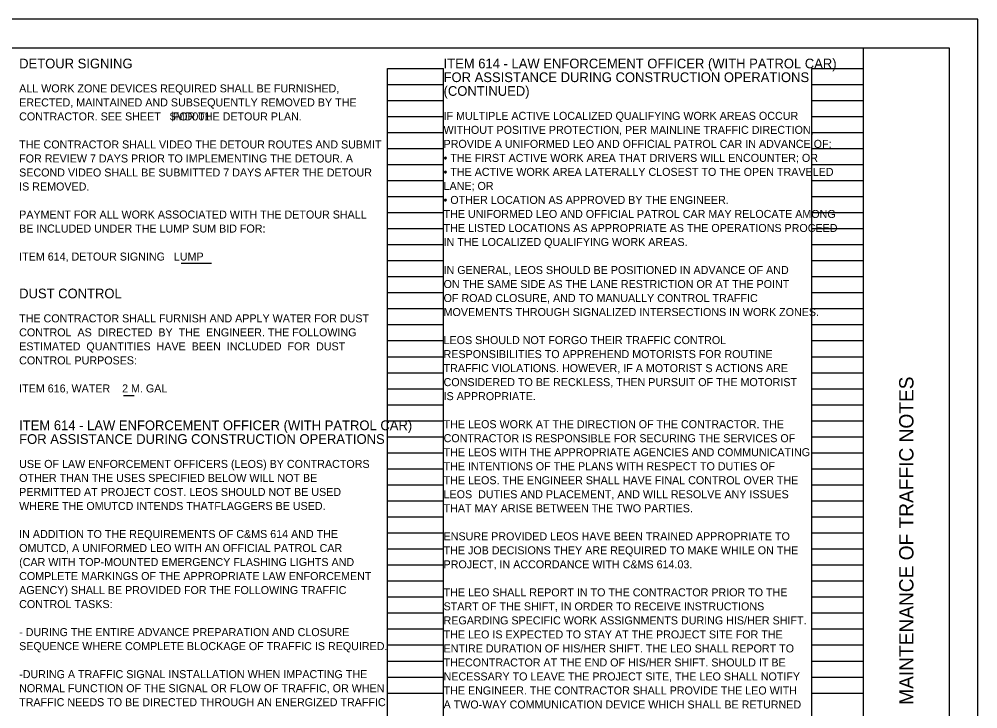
# Model space of a CAD drawing. Extents: x 0 to 69, y 0 to 22.
# Drawn here: x 17.24 to 34, y 9.94 to 22 of the extents above; entities that cross this region are included whole.
import ezdxf

# ---------------------------------------------------------------- set-up
doc = ezdxf.new("R2010")
doc.units = 0
for name, color, linetype in [('GM_X_City_Street', 7, 'Continuous'), ('GM_X_Corporation_Text', 7, 'Continuous'), ('SH_Border', 7, 'Continuous'), ('SH_Cut_Line', 7, 'Continuous'), ('SH_Data', 7, 'Continuous'), ('SH_Text', 7, 'Continuous')]:
    doc.layers.add(name, color=color, linetype=linetype)

msp = doc.modelspace()

# ---------------------------------------------------------------- linework, layer by layer
at = {"layer": 'GM_X_City_Street'}
for p, q in [((23.68, 0.98), (23.68, 21.14)), ((23.68, 21.14), (24.66, 21.14)), ((24.66, 0.98), (24.66, 21.14)), ((31.1, 0.98), (31.1, 21.14)), ((31.1, 21.14), (32, 21.14)), ((32, 0.98), (32, 21.14)), ((23.68, 20.86), (24.66, 20.86)), ((31.1, 20.86), (32, 20.86)), ((23.68, 20.58), (24.66, 20.58)), ((31.1, 20.58), (32, 20.58)), ((23.68, 20.3), (24.66, 20.3)), ((31.1, 20.3), (32, 20.3)), ((23.68, 20.02), (24.66, 20.02)), ((31.1, 20.02), (32, 20.02)), ((23.68, 19.74), (24.66, 19.74)), ((31.1, 19.74), (32, 19.74)), ((23.68, 19.46), (24.66, 19.46)), ((31.1, 19.46), (32, 19.46)), ((23.68, 19.18), (24.66, 19.18)), ((31.1, 19.18), (32, 19.18)), ((23.68, 18.9), (24.66, 18.9)), ((31.1, 18.9), (32, 18.9)), ((23.68, 18.62), (24.66, 18.62)), ((31.1, 18.62), (32, 18.62)), ((23.68, 18.34), (24.66, 18.34)), ((31.1, 18.34), (32, 18.34)), ((23.68, 18.06), (24.66, 18.06)), ((31.1, 18.06), (32, 18.06)), ((23.68, 17.78), (24.66, 17.78)), ((31.1, 17.78), (32, 17.78)), ((23.68, 17.5), (24.66, 17.5)), ((31.1, 17.5), (32, 17.5)), ((23.68, 17.22), (24.66, 17.22)), ((31.1, 17.22), (32, 17.22)), ((23.68, 16.94), (24.66, 16.94)), ((31.1, 16.94), (32, 16.94)), ((23.68, 16.66), (24.66, 16.66)), ((31.1, 16.66), (32, 16.66)), ((23.68, 16.38), (24.66, 16.38)), ((31.1, 16.38), (32, 16.38)), ((23.68, 16.1), (24.66, 16.1)), ((31.1, 16.1), (32, 16.1)), ((23.68, 15.82), (24.66, 15.82)), ((31.1, 15.82), (32, 15.82)), ((23.68, 15.54), (24.66, 15.54)), ((31.1, 15.54), (32, 15.54)), ((23.68, 15.26), (24.66, 15.26)), ((31.1, 15.26), (32, 15.26)), ((23.68, 14.98), (24.66, 14.98)), ((31.1, 14.98), (32, 14.98)), ((23.68, 14.7), (24.66, 14.7)), ((31.1, 14.7), (32, 14.7)), ((23.68, 14.42), (24.66, 14.42)), ((31.1, 14.42), (32, 14.42)), ((23.68, 14.14), (24.66, 14.14)), ((31.1, 14.14), (32, 14.14)), ((23.68, 13.86), (24.66, 13.86)), ((31.1, 13.86), (32, 13.86)), ((23.68, 13.58), (24.66, 13.58)), ((31.1, 13.58), (32, 13.58)), ((23.68, 13.3), (24.66, 13.3)), ((31.1, 13.3), (32, 13.3)), ((23.68, 13.02), (24.66, 13.02)), ((31.1, 13.02), (32, 13.02)), ((23.68, 12.74), (24.66, 12.74)), ((31.1, 12.74), (32, 12.74)), ((23.68, 12.46), (24.66, 12.46)), ((31.1, 12.46), (32, 12.46)), ((23.68, 12.18), (24.66, 12.18)), ((31.1, 12.18), (32, 12.18)), ((23.68, 11.9), (24.66, 11.9)), ((31.1, 11.9), (32, 11.9)), ((23.68, 11.62), (24.66, 11.62)), ((31.1, 11.62), (32, 11.62)), ((23.68, 11.34), (24.66, 11.34)), ((31.1, 11.34), (32, 11.34)), ((23.68, 11.06), (24.66, 11.06)), ((31.1, 11.06), (32, 11.06)), ((23.68, 10.78), (24.66, 10.78)), ((31.1, 10.78), (32, 10.78)), ((23.68, 10.5), (24.66, 10.5)), ((31.1, 10.5), (32, 10.5)), ((23.68, 10.22), (24.66, 10.22)), ((31.1, 10.22), (32, 10.22))]:
    msp.add_line(p, q, dxfattribs=at)
at = {"layer": 'GM_X_Corporation_Text'}
for p, q in [((20.072, 17.735), (20.603, 17.735)), ((19.067, 15.42), (19.248, 15.42))]:
    msp.add_line(p, q, dxfattribs=at)
at = {"layer": 'SH_Border'}
msp.add_line((32, 0.5), (32, 21.5), dxfattribs=at)
msp.add_lwpolyline([(1.5, 21.5), (33.5, 21.5), (33.5, 0.5), (1.5, 0.5)], close=True, dxfattribs=at)
at = {"layer": 'SH_Cut_Line'}
msp.add_lwpolyline([(0, 0), (34, 0), (34, 22), (0, 22)], close=True, dxfattribs=at)

# ---------------------------------------------------------------- texts
at = {"layer": 'SH_Data'}
msp.add_text('MAINTENANCE OF TRAFFIC NOTES', height=0.25, rotation=90, dxfattribs=at).set_placement((32.875, 10.014))
at = {"layer": 'SH_Text'}
for s, height, p in [('DETOUR SIGNING', 0.17, (17.24, 21.14)), ('ITEM 614 - LAW ENFORCEMENT OFFICER (WITH PATROL CAR)', 0.17, (24.66, 21.14)), ('FOR ASSISTANCE DURING CONSTRUCTION OPERATIONS', 0.17, (24.66, 20.9)), ('ALL WORK ZONE DEVICES REQUIRED SHALL BE FURNISHED, ', 0.14, (17.24, 20.72)), ('(CONTINUED)', 0.17, (24.66, 20.66)), ('ERECTED, MAINTAINED AND SUBSEQUENTLY REMOVED BY THE ', 0.14, (17.24, 20.475)), ('CONTRACTOR. SEE SHEET    FOR THE DETOUR PLAN.', 0.14, (17.24, 20.23)), ('$MD001', 0.14, (19.873, 20.23)), ('IF MULTIPLE ACTIVE LOCALIZED QUALIFYING WORK AREAS OCCUR ', 0.14, (24.66, 20.24)), ('WITHOUT POSITIVE PROTECTION, PER MAINLINE TRAFFIC DIRECTION, ', 0.14, (24.66, 19.995)), ('THE CONTRACTOR SHALL VIDEO THE DETOUR ROUTES AND SUBMIT ', 0.14, (17.24, 19.74)), ('PROVIDE A UNIFORMED LEO AND OFFICIAL PATROL CAR IN ADVANCE OF:', 0.14, (24.66, 19.75)), ('FOR REVIEW 7 DAYS PRIOR TO IMPLEMENTING THE DETOUR. A ', 0.14, (17.24, 19.495)), ('• THE FIRST ACTIVE WORK AREA THAT DRIVERS WILL ENCOUNTER; OR', 0.14, (24.66, 19.505)), ('SECOND VIDEO SHALL BE SUBMITTED 7 DAYS AFTER THE DETOUR ', 0.14, (17.24, 19.25)), ('• THE ACTIVE WORK AREA LATERALLY CLOSEST TO THE OPEN TRAVELED ', 0.14, (24.66, 19.26)), ('IS REMOVED.', 0.14, (17.24, 19.005)), ('LANE; OR', 0.14, (24.66, 19.015)), ('• OTHER LOCATION AS APPROVED BY THE ENGINEER.', 0.14, (24.66, 18.77)), ('PAYMENT FOR ALL WORK ASSOCIATED WITH THE DETOUR SHALL ', 0.14, (17.24, 18.515)), ('THE UNIFORMED LEO AND OFFICIAL PATROL CAR MAY RELOCATE AMONG ', 0.14, (24.66, 18.525)), ('BE INCLUDED UNDER THE LUMP SUM BID FOR:', 0.14, (17.24, 18.27)), ('THE LISTED LOCATIONS AS APPROPRIATE AS THE OPERATIONS PROCEED ', 0.14, (24.66, 18.28)), ('IN THE LOCALIZED QUALIFYING WORK AREAS.', 0.14, (24.66, 18.035)), ('ITEM 614, DETOUR SIGNING   LUMP', 0.14, (17.24, 17.78)), ('IN GENERAL, LEOS SHOULD BE POSITIONED IN ADVANCE OF AND ', 0.14, (24.66, 17.545)), ('ON THE SAME SIDE AS THE LANE RESTRICTION OR AT THE POINT ', 0.14, (24.66, 17.3)), ('DUST CONTROL', 0.17, (17.24, 17.12)), ('OF ROAD CLOSURE, AND TO MANUALLY CONTROL TRAFFIC ', 0.14, (24.66, 17.055)), ('MOVEMENTS THROUGH SIGNALIZED INTERSECTIONS IN WORK ZONES.', 0.14, (24.66, 16.81)), ('THE CONTRACTOR SHALL FURNISH AND APPLY WATER FOR DUST', 0.14, (17.24, 16.7)), ('CONTROL  AS  DIRECTED  BY  THE  ENGINEER. THE FOLLOWING', 0.14, (17.24, 16.455)), ('LEOS SHOULD NOT FORGO THEIR TRAFFIC CONTROL ', 0.14, (24.66, 16.32)), ('ESTIMATED  QUANTITIES  HAVE  BEEN  INCLUDED  FOR  DUST', 0.14, (17.24, 16.21)), ('CONTROL PURPOSES: ', 0.14, (17.24, 15.965)), ('RESPONSIBILITIES TO APPREHEND MOTORISTS FOR ROUTINE ', 0.14, (24.66, 16.075)), ('TRAFFIC VIOLATIONS. HOWEVER, IF A MOTORIST S ACTIONS ARE ', 0.14, (24.66, 15.83)), ('ITEM 616, WATER    2 M. GAL ', 0.14, (17.24, 15.475)), ('CONSIDERED TO BE RECKLESS, THEN PURSUIT OF THE MOTORIST ', 0.14, (24.66, 15.585)), ('IS APPROPRIATE.', 0.14, (24.66, 15.34)), ('ITEM 614 - LAW ENFORCEMENT OFFICER (WITH PATROL CAR)', 0.17, (17.24, 14.815)), ('THE LEOS WORK AT THE DIRECTION OF THE CONTRACTOR. THE ', 0.14, (24.66, 14.85)), ('FOR ASSISTANCE DURING CONSTRUCTION OPERATIONS', 0.17, (17.24, 14.575)), ('CONTRACTOR IS RESPONSIBLE FOR SECURING THE SERVICES OF ', 0.14, (24.66, 14.605)), ('THE LEOS WITH THE APPROPRIATE AGENCIES AND COMMUNICATING ', 0.14, (24.66, 14.36)), ('USE OF LAW ENFORCEMENT OFFICERS (LEOS) BY CONTRACTORS ', 0.14, (17.24, 14.155)), ('THE INTENTIONS OF THE PLANS WITH RESPECT TO DUTIES OF ', 0.14, (24.66, 14.115)), ('OTHER THAN THE USES SPECIFIED BELOW WILL NOT BE ', 0.14, (17.24, 13.91)), ('THE LEOS. THE ENGINEER SHALL HAVE FINAL CONTROL OVER THE', 0.14, (24.66, 13.87)), ('PERMITTED AT PROJECT COST. LEOS SHOULD NOT BE USED ', 0.14, (17.24, 13.665)), ('LEOS  DUTIES AND PLACEMENT, AND WILL RESOLVE ANY ISSUES ', 0.14, (24.66, 13.625)), ('WHERE THE OMUTCD INTENDS THATFLAGGERS BE USED.', 0.14, (17.24, 13.42)), ('THAT MAY ARISE BETWEEN THE TWO PARTIES.', 0.14, (24.66, 13.38)), ('IN ADDITION TO THE REQUIREMENTS OF C&MS 614 AND THE ', 0.14, (17.24, 12.93)), ('ENSURE PROVIDED LEOS HAVE BEEN TRAINED APPROPRIATE TO ', 0.14, (24.66, 12.89)), ('OMUTCD, A UNIFORMED LEO WITH AN OFFICIAL PATROL CAR ', 0.14, (17.24, 12.685)), ('THE JOB DECISIONS THEY ARE REQUIRED TO MAKE WHILE ON THE ', 0.14, (24.66, 12.645)), ('(CAR WITH TOP-MOUNTED EMERGENCY FLASHING LIGHTS AND ', 0.14, (17.24, 12.44)), ('PROJECT, IN ACCORDANCE WITH C&MS 614.03.', 0.14, (24.66, 12.4)), ('COMPLETE MARKINGS OF THE APPROPRIATE LAW ENFORCEMENT ', 0.14, (17.24, 12.195)), ('AGENCY) SHALL BE PROVIDED FOR THE FOLLOWING TRAFFIC ', 0.14, (17.24, 11.95)), ('THE LEO SHALL REPORT IN TO THE CONTRACTOR PRIOR TO THE ', 0.14, (24.66, 11.91)), ('CONTROL TASKS:', 0.14, (17.24, 11.705)), ('START OF THE SHIFT, IN ORDER TO RECEIVE INSTRUCTIONS ', 0.14, (24.66, 11.665)), ('REGARDING SPECIFIC WORK ASSIGNMENTS DURING HIS/HER SHIFT. ', 0.14, (24.66, 11.42)), ('- DURING THE ENTIRE ADVANCE PREPARATION AND CLOSURE ', 0.14, (17.24, 11.215)), ('THE LEO IS EXPECTED TO STAY AT THE PROJECT SITE FOR THE ', 0.14, (24.66, 11.175)), ('SEQUENCE WHERE COMPLETE BLOCKAGE OF TRAFFIC IS REQUIRED.', 0.14, (17.24, 10.97)), ('ENTIRE DURATION OF HIS/HER SHIFT. THE LEO SHALL REPORT TO ', 0.14, (24.66, 10.93)), ('THECONTRACTOR AT THE END OF HIS/HER SHIFT. SHOULD IT BE ', 0.14, (24.66, 10.685)), ('-DURING A TRAFFIC SIGNAL INSTALLATION WHEN IMPACTING THE ', 0.14, (17.24, 10.48)), ('NECESSARY TO LEAVE THE PROJECT SITE, THE LEO SHALL NOTIFY ', 0.14, (24.66, 10.44)), ('NORMAL FUNCTION OF THE SIGNAL OR FLOW OF TRAFFIC, OR WHEN ', 0.14, (17.24, 10.235)), ('THE ENGINEER. THE CONTRACTOR SHALL PROVIDE THE LEO WITH ', 0.14, (24.66, 10.195)), ('TRAFFIC NEEDS TO BE DIRECTED THROUGH AN ENERGIZED TRAFFIC ', 0.14, (17.24, 9.99)), ('A TWO-WAY COMMUNICATION DEVICE WHICH SHALL BE RETURNED ', 0.14, (24.66, 9.95))]:
    msp.add_text(s, height=height, dxfattribs=at).set_placement(p)

doc.saveas('drawing.dxf')
